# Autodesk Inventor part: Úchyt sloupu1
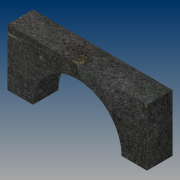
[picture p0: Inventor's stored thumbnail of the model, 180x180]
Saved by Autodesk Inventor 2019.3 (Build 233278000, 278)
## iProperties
Created: 2019-03
Part Number: Úchyt sloupu1
Material: Ocel
Document SubType Name: Modeling
Designer: B-hon
Density: 7.85 g/cm^3
Appearance: Plech
Author: B-hon
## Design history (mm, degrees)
sketch "Náčrt1"
  geometry: L1 (-55, 45)-(55, 45); L2 (55, 45)-(55, 0); L3 (-55, 0)-(-55, 45); L4 (55, 0)-(35, 0); L5 (-35, 0)-(-55, 0); A1 r 35 centre (0, 0) between (35, 0) and (-35, 0); 1 further point
  constraints: 10 end point, 3 parallel, 2 horizontal alignment, 2 point on circle, 1 centre point, 1 coincident, 1 horizontal, 1 perpendicular
  dimensions: "d0" = 70 diameter of A1; "d1" = 110 distance of L1.start L1.end; "d2" = 20 distance of L2.end L4.end; "d3" = 45 distance of L1.end L2.end
extrude "Vysunutí1" new body sketch "Náčrt1" distance "d4" = 20; taper "d5" = 0 deg
sketch "Náčrt2"
  geometry: L1 (0, 0)-(0, 20) reference; L2 (20, 0)-(0, 0) reference; 3 further points
  constraints: 1 horizontal alignment
  dimensions: "d6" = 90 distance of point (100, 10) point (10, 10); "d7" = 10 distance from line of L1 point (10, 10); "d8" = 10 distance from line of L2 point (10, 10)
hole "Díra1" sketch "Náčrt2" at (10, 10), (100, 10) diameter "d9" = 8.376; stored, may be unused: countersink angle "d13" = 90 deg, drill point angle "d15" = 118 deg; dims "d10" = 35, "d11" = 10, "d12" = 2, "d14" = 40
node "Těleso1"
